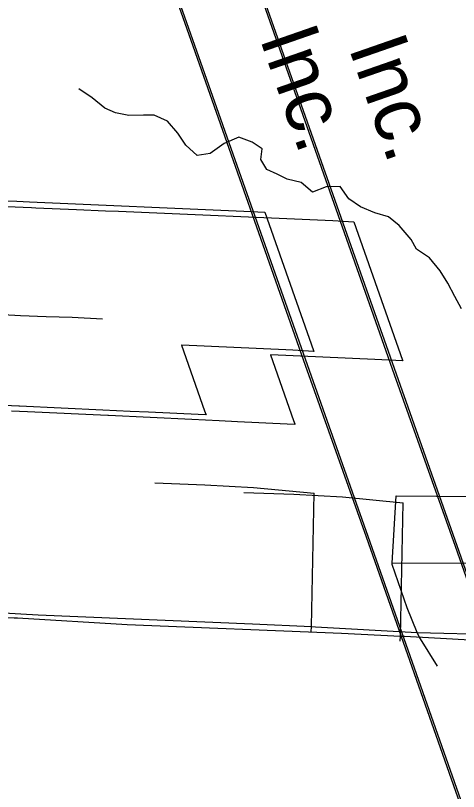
# Model space of a CAD drawing. Extents: x -38.2 to 41.9, y -4 to 24.9.
# Drawn here: x 6.651 to 7.082, y 17.504 to 18.257 of the extents above; entities that cross this region are included whole.
import ezdxf

# ---------------------------------------------------------------- set-up
doc = ezdxf.new("R2010")
doc.units = 0
for name, color, linetype in [('Default', 7, 'Continuous'), ('GM_X_City_Street', 7, 'Continuous'), ('GM_X_County_Road', 7, 'Continuous'), ('GM_X_Interchange_Ramps', 7, 'Continuous'), ('GM_X_Interstate_Location', 7, 'Continuous'), ('GM_X_Minor_River', 7, 'Continuous'), ('GM_X_Rail_Line', 7, 'Continuous'), ('GM_X_Rail_Line_Text', 7, 'Continuous'), ('GM_X_State_Location', 7, 'Continuous'), ('GM_X_State_Route', 7, 'Continuous')]:
    doc.layers.add(name, color=color, linetype=linetype)

msp = doc.modelspace()

# ---------------------------------------------------------------- linework, layer by layer
at = {"layer": 'Default'}
msp.add_lwpolyline([(6.62383, 18.07807), (6.6523, 18.07686), (6.66477, 18.07633), (6.87308, 18.06726), (6.89337, 18.06618), (6.94082, 17.93183), (6.94108, 17.93109), (6.92074, 17.93208), (6.91397, 17.93241), (6.81267, 17.93694), (6.81241, 17.93695), (6.83489, 17.87322), (6.83605, 17.87004), (6.83631, 17.8693), (6.82879, 17.86965), (6.78042, 17.8719), (6.76276, 17.87274), (6.73617, 17.874), (6.65514, 17.87785), (6.65429, 17.87789), (6.57634, 17.88156)], dxfattribs=at)
at = {"layer": 'GM_X_City_Street'}
msp.add_line((7.02097, 17.79062), (7.16987, 17.78976), dxfattribs=at)
for points in [[(6.78658, 17.80324), (6.83506, 17.80146), (6.88239, 17.79892), (6.94143, 17.7932)], [(6.93859, 17.65868), (6.9387, 17.66371), (6.94143, 17.7932)], [(7.06132, 17.62528), (7.04478, 17.65173), (7.04312, 17.65438), (7.04159, 17.65808), (7.03172, 17.68187), (7.0171, 17.72422), (7.01717, 17.72544), (7.02097, 17.79062)], [(7.01717, 17.72544), (7.125, 17.7257), (7.17694, 17.72255)]]:
    msp.add_lwpolyline(points, dxfattribs=at)
at = {"layer": 'GM_X_County_Road'}
msp.add_lwpolyline([(6.59451, 18.07374), (6.66657, 18.07075), (6.67102, 18.07056), (6.71031, 18.06888), (6.73878, 18.06767), (6.75124, 18.06714), (6.95956, 18.05807), (6.97985, 18.05699), (7.02729, 17.92264), (7.02756, 17.9219), (7.00722, 17.9229), (7.00045, 17.92322), (6.89915, 17.92775), (6.89889, 17.92776), (6.92137, 17.86403), (6.92252, 17.86085), (6.92279, 17.86011), (6.91526, 17.86046), (6.8669, 17.86272), (6.84924, 17.86355), (6.82265, 17.86481), (6.74162, 17.86866), (6.74077, 17.8687), (6.66281, 17.87237), (6.6474, 17.87309)], dxfattribs=at)
at = {"layer": 'GM_X_Interchange_Ramps'}
for points in [[(6.50725, 17.67817), (6.51257, 17.67801), (6.57399, 17.67547), (6.65001, 17.67234), (6.65294, 17.67217)], [(6.65294, 17.67217), (6.75956, 17.66585), (6.96798, 17.65729), (7.02517, 17.65452), (7.02912, 17.65433), (7.12807, 17.6489), (7.20547, 17.64692), (7.22184, 17.6465), (7.27164, 17.64343)]]:
    msp.add_lwpolyline(points, dxfattribs=at)
at = {"layer": 'GM_X_Interstate_Location'}
for points in [[(6.87306, 17.79405), (6.92154, 17.79227), (6.96887, 17.78973), (7.02791, 17.78401)], [(7.02507, 17.64949), (7.02517, 17.65452), (7.02791, 17.78401)]]:
    msp.add_lwpolyline(points, dxfattribs=at)
at = {"layer": 'GM_X_Minor_River'}
msp.add_lwpolyline([(7.08448, 17.97252), (7.07804, 17.98429), (7.07122, 17.99719), (7.06403, 18.00933), (7.05342, 18.02186), (7.04093, 18.03021), (7.03563, 18.03969), (7.02389, 18.05336), (7.01367, 18.06171), (7.00042, 18.06551), (6.98641, 18.07158), (6.97505, 18.07918), (6.96672, 18.09132), (6.9531, 18.09095), (6.93986, 18.08564), (6.92887, 18.09513), (6.91525, 18.09818), (6.90541, 18.10311), (6.89557, 18.10767), (6.8895, 18.11754), (6.89101, 18.12778), (6.88117, 18.13423), (6.8683, 18.13917), (6.85392, 18.13311), (6.8403, 18.12325), (6.82781, 18.12136), (6.81683, 18.13123), (6.80888, 18.14299), (6.79903, 18.15476), (6.78578, 18.16045), (6.77556, 18.16046), (6.76118, 18.16009), (6.74831, 18.16275), (6.73809, 18.16731), (6.7256, 18.17718), (6.71273, 18.1859)], dxfattribs=at)
at = {"layer": 'GM_X_Rail_Line'}
for points in [[(7.7706, 16.28366), (7.74361, 16.31959), (7.68526, 16.38726), (7.53261, 16.56097), (7.48784, 16.61181), (7.44957, 16.65586), (7.42686, 16.68437), (7.41112, 16.70515), (7.39494, 16.72742), (7.37919, 16.75045), (7.35203, 16.79365), (7.31773, 16.85496), (7.29487, 16.90307), (7.2772, 16.94465), (7.26621, 16.97389), (7.24279, 17.03883), (7.20306, 17.15103), (7.17446, 17.2327), (6.99217, 17.75064), (6.93302, 17.91744), (6.82378, 18.22738), (6.69158, 18.60188)], [(7.77212, 16.2848), (7.74509, 16.32078), (7.6867, 16.3885), (7.53404, 16.56222), (7.48928, 16.61305), (7.45104, 16.65707), (7.42836, 16.68553), (7.41265, 16.70628), (7.3965, 16.72851), (7.38079, 16.75148), (7.35366, 16.79461), (7.31943, 16.85583), (7.2966, 16.90385), (7.27896, 16.94535), (7.268, 16.97454), (7.24458, 17.03946), (7.20486, 17.15166), (7.17625, 17.23332), (6.99396, 17.75127), (6.93481, 17.91807), (6.82557, 18.22801), (6.69338, 18.60251)]]:
    msp.add_lwpolyline(points, dxfattribs=at)
at = {"layer": 'GM_X_Rail_Line_Text'}
for points in [[(7.85708, 16.27447), (7.83009, 16.3104), (7.77174, 16.37807), (7.61908, 16.55178), (7.57432, 16.60262), (7.53605, 16.64667), (7.51334, 16.67518), (7.4976, 16.69596), (7.48142, 16.71823), (7.46567, 16.74126), (7.4385, 16.78446), (7.40421, 16.84577), (7.38134, 16.89388), (7.36367, 16.93546), (7.35269, 16.9647), (7.32926, 17.02964), (7.28954, 17.14184), (7.26094, 17.22351), (7.07865, 17.74146), (7.0195, 17.90825), (6.91025, 18.21819), (6.77806, 18.5927)], [(7.8586, 16.27561), (7.83157, 16.31159), (7.77318, 16.37931), (7.62052, 16.55303), (7.57576, 16.60387), (7.53752, 16.64788), (7.51484, 16.67634), (7.49913, 16.69709), (7.48297, 16.71932), (7.46726, 16.7423), (7.44014, 16.78543), (7.4059, 16.84664), (7.38308, 16.89466), (7.36544, 16.93616), (7.35447, 16.96536), (7.33106, 17.03027), (7.29134, 17.14247), (7.26273, 17.22413), (7.08044, 17.74208), (7.02129, 17.90888), (6.91205, 18.21882), (6.77985, 18.59332)]]:
    msp.add_lwpolyline(points, dxfattribs=at)
at = {"layer": 'GM_X_State_Location'}
msp.add_lwpolyline([(6.63928, 17.96679), (6.65608, 17.96603), (6.68084, 17.96505), (6.70616, 17.96432), (6.73586, 17.96264)], dxfattribs=at)
at = {"layer": 'GM_X_State_Route'}
msp.add_lwpolyline([(6.56647, 17.68135), (6.67309, 17.67504), (6.88151, 17.66648), (6.9387, 17.66371), (6.94264, 17.66352), (7.04159, 17.65808), (7.11899, 17.65611), (7.13536, 17.65569), (7.18516, 17.65262)], dxfattribs=at)

# ---------------------------------------------------------------- texts
at = {"layer": 'GM_X_City_Street'}
msp.add_text('Inc.', height=0.056629, rotation=289.1788, dxfattribs=at).set_placement((6.97457, 18.22643))
at = {"layer": 'GM_X_Rail_Line_Text'}
msp.add_text('Inc.', height=0.056629, rotation=289.1788, dxfattribs=at).set_placement((6.88809, 18.23562))

doc.saveas('drawing.dxf')
